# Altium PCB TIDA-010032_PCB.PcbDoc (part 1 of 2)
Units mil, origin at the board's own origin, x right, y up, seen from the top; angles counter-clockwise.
Board outline 5930.03 x 5930.03 mil, 2 copper layers (Top Layer, Bottom Layer), stack 62 mil thick; 61 components, 49 nets, 261 pads, 71 vias.
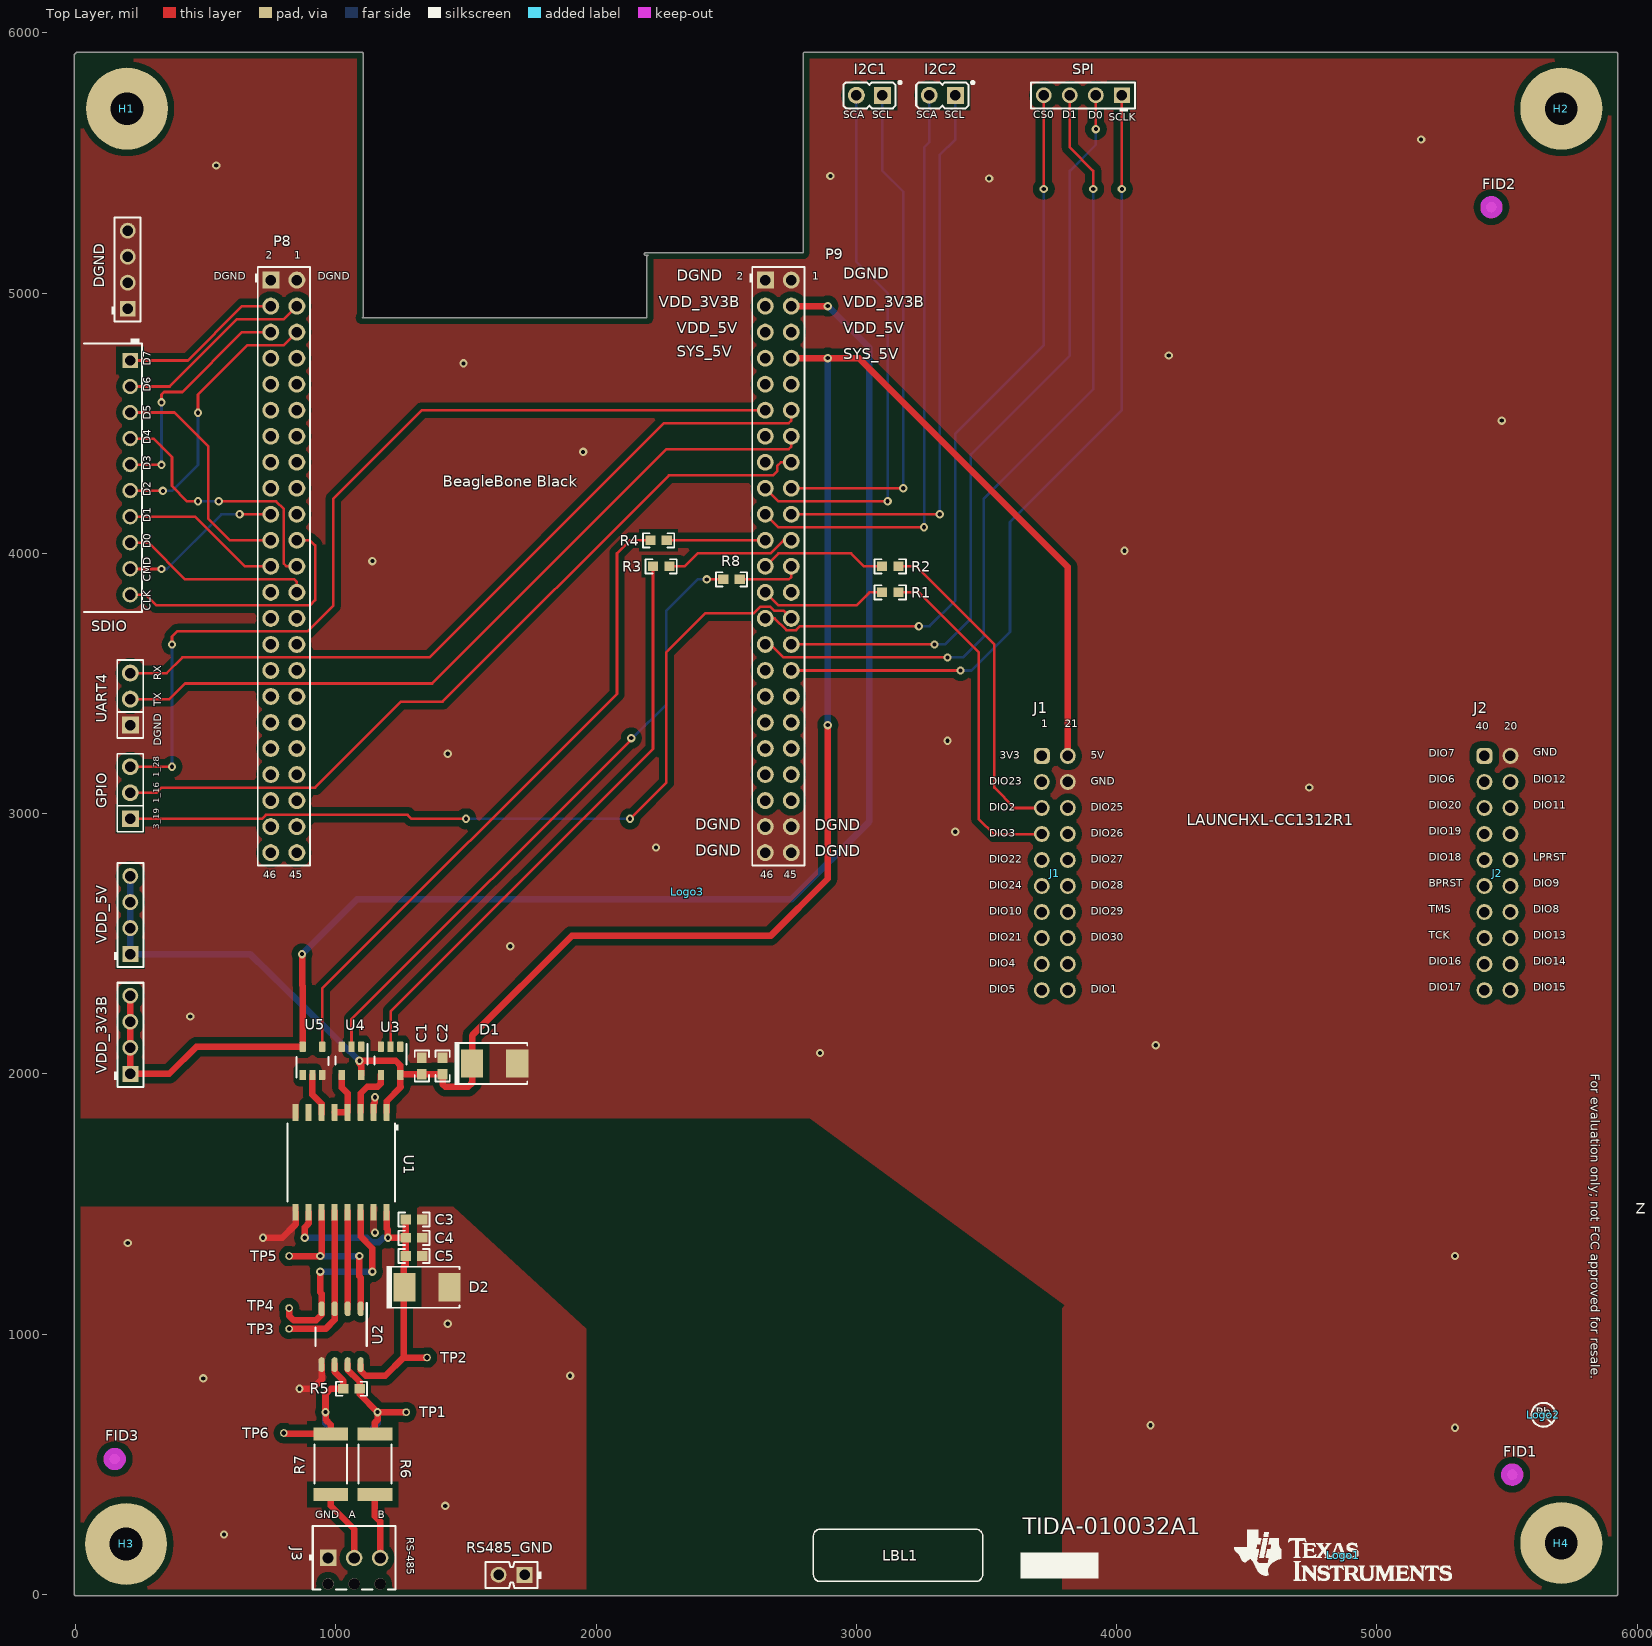
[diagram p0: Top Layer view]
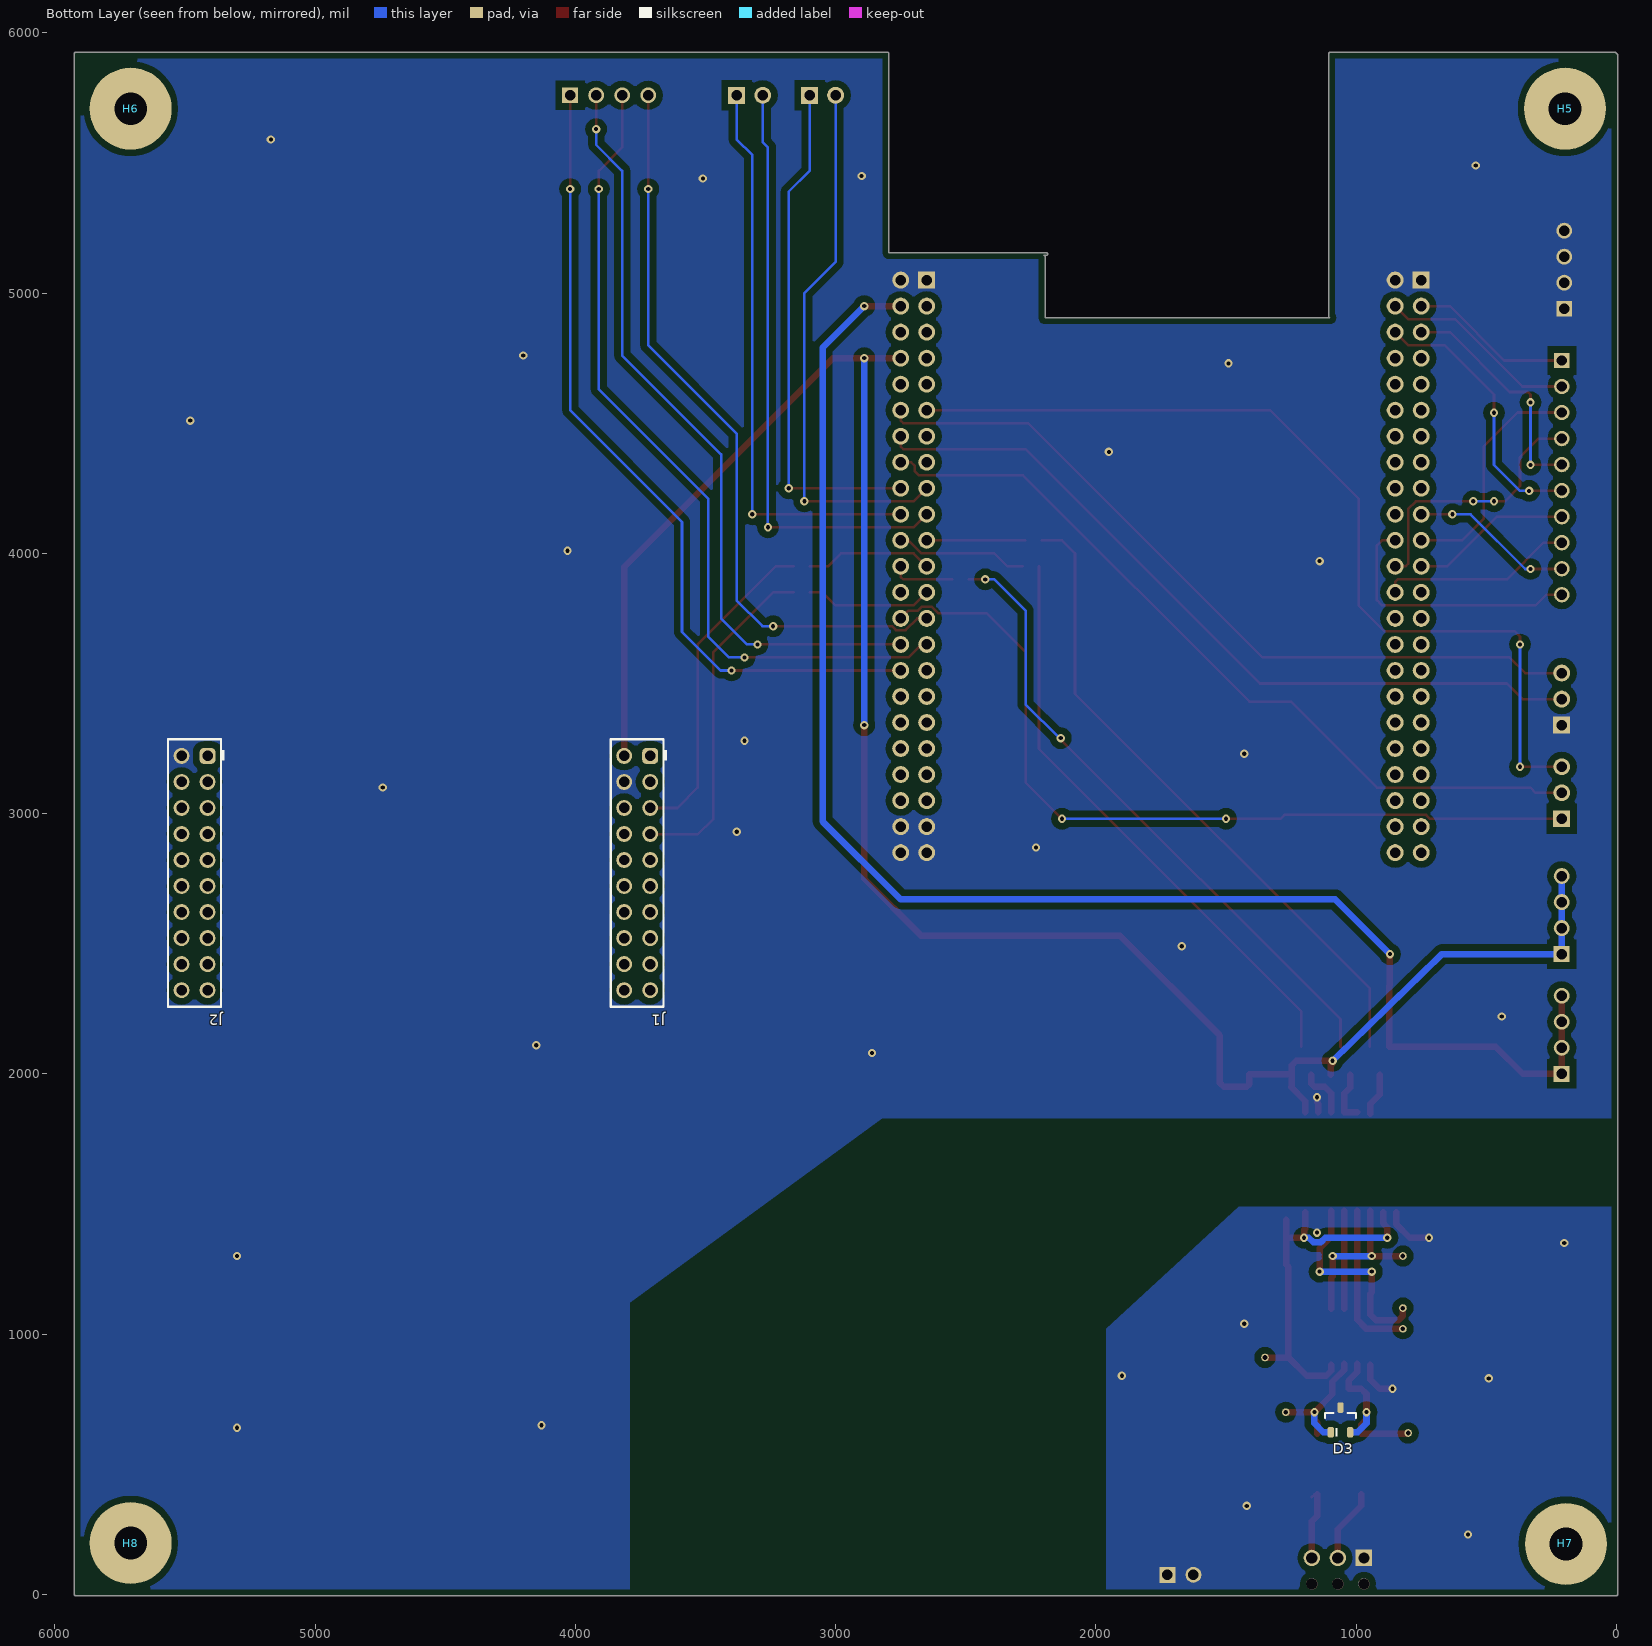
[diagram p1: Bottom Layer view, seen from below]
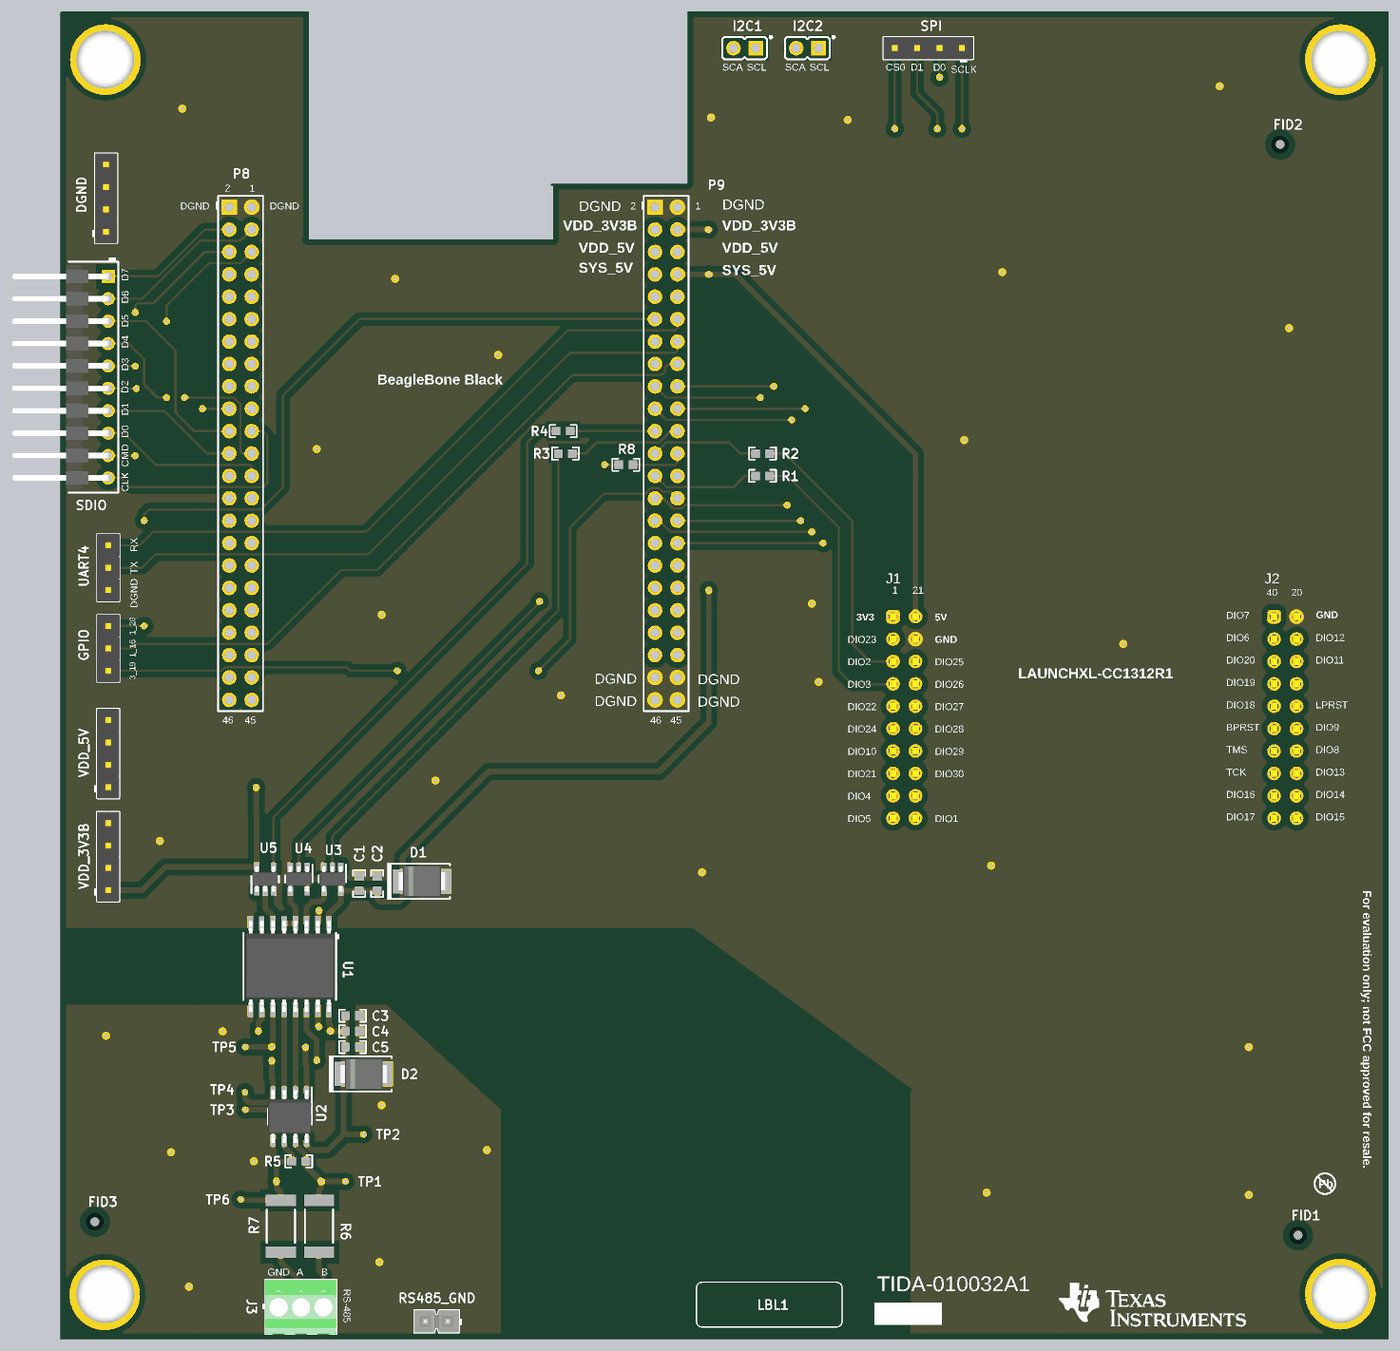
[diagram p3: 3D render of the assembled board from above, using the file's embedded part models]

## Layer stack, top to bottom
Top Solder: solder mask 0.4, Solder Resist, Dk 3.5
Top Layer: signal copper 1.4
Dielectric1: core 59.2, FR-4, Dk 4.8
Bottom Layer: signal copper 1.4
Bottom Solder: solder mask 0.4, Solder Resist, Dk 3.5

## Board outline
0,-5.02 cw(c0,0) -5.01,0 -5.01,5915.02 cw(c0,5915.02) -0.03,5920.03 cw(c4.99,5920) 4.99,5925.02 1100,5925.02 cw(c1100,5920) 1105.02,5920 1105.02,4910 cw(c1100,4910) 1100.55,4905.02 2194.99,4905.02 2194.99,5140 cw(c2200,5140) 2199.45,5144.98 2190,5144.98 cw(c2190,5150) 2190,5155.02 2794.99,5155.02 2794.99,5920 cw(c2800,5920) 2800,5925.02 5920,5925.02 cw(c5920,5920) 5925.02,5920 5925.02,0 cw(c5920,0) 5920,-5.02

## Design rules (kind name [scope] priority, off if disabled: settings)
AcuteAngle [All] p1: minimum=4.50000000000000E+0001 checktracksonly=FALSE
AssemblyTestPointUsage [All] p1: valid=2
BoardOutlineClearance BoardOutlineClearance_MountingHoles [OnCopper and InComponentClass('Mounting Holes')] p1: gap=40
BoardOutlineClearance BoardOutlineClearance_Poly [OnCopper and IsPoly] p2: gap=25
BoardOutlineClearance [OnCopper and Not InComponentClass('Logo') and not InComponentClass('FiducialMark') and not InRegion(1000,500,4000,800) and not InPoly] p3: gap=15
Clearance Clearance_Keepouts [((IsTrack Or IsArc) And Not InPoly) And IsFree and IsKeepOut vs ((IsTrack Or IsArc) And Not InPoly) And IsFree and IsKeepOut] p1: gap=0
Clearance Clearance_Poly [InPolygon] p2: gap=25
Clearance [All] p3: gap=7.87
ComponentClearance ComponentClearance_MountingHoles_FiducialMarks [InComponentClass('Mounting Holes') vs InComponentClass('FiducialMark')] p1: gap=50 collisioncheckmode=3 verticalgap=10 showdistances=FALSE
ComponentClearance ComponentClearance_Shunt [InComponentClass('Header') vs InComponentClass('Shunt')] p2: gap=0 collisioncheckmode=3 verticalgap=0 showdistances=FALSE
ComponentClearance ComponentClearance_Logo [InComponentClass('Logo')] p3: gap=50 collisioncheckmode=3 verticalgap=10 showdistances=FALSE
ComponentClearance ComponentClearance_ScrewToNut [(HasFootprint('NY PMS 440 0025 PH')) vs (HasFootprint('Keystone_1902C'))] p4: gap=5 collisioncheckmode=3 verticalgap=10 showdistances=FALSE
ComponentClearance ComponentClearance_MountingHoles [InComponentClass('Mounting Holes')] p5: gap=250 collisioncheckmode=3 verticalgap=100000 showdistances=FALSE
ComponentClearance ComponentClearance_SmallPassives [HasFootprint('0201*') or HasFootprint('0402*') or HasFootprint('0508') or HasFootprint('0603*') or HasFootprint('0612') or HasFootprint('0805*') or HasFootprint('0815*') or HasFootprint('0830*') or HasFootprint('1206*') or HasFootprint('1210*') or HasFootprint('1808*') or HasFootprint('1812*') or HasFootprint('1825*') or HasFootprint('2010*') or HasFootprint('2220*') or HasFootprint('2225*') or HasFootprint('2512*') or HasFootprint('2728*') or HasFootprint('3518*') vs HasFootprint('0201*') or HasFootprint('0402*') or HasFootprint('0508') or HasFootprint('0603*') or HasFootprint('0612') or HasFootprint('0805*') or HasFootprint('0815*') or HasFootprint('0830*') or HasFootprint('1206*') or HasFootprint('1210*') or HasFootprint('1808*') or HasFootprint('1812*') or HasFootprint('1825*') or HasFootprint('2010*') or HasFootprint('2220*') or HasFootprint('2225*') or HasFootprint('2512*') or HasFootprint('2728*') or HasFootprint('3518*')] p6: gap=14.96 collisioncheckmode=3 verticalgap=10 showdistances=FALSE
ComponentClearance ComponentClearance_THtoSMT [IsThruComponent vs IsSMTComponent] p7: gap=40 collisioncheckmode=3 verticalgap=30 showdistances=FALSE
ComponentClearance ComponentClearance_THtoTH [IsThruComponent vs IsThruComponent] p8: gap=30 collisioncheckmode=3 verticalgap=30 showdistances=FALSE
ComponentClearance [All] p9: gap=30 collisioncheckmode=3 verticalgap=10 showdistances=FALSE
DiffPairsRouting [All] p1: maxlimit=100 minlimit=10 mostfreqgap=10 toplayer_minwidth=15 toplayer_maxwidth=15 toplayer_prefwidth=15 bottomlayer_minwidth=15 bottomlayer_maxwidth=15 bottomlayer_prefwidth=15 maxuncoupledlength=1000
FabricationTestPointUsage TestPointUsage [All] p1: valid=2 allowmultiple=FALSE
FabricationTestpoint Testpoint [All] p1: side=3 testpointundercomponent=TRUE minsize=40 maxsize=100 preferedsize=60 minholesize=0 maxholesize=40 preferedholesize=32 testpointgrid=1 allowsidetop=TRUE allowsidebottom=TRUE usegrid=TRUE gridtolerance=0.01
FanoutControl Fanout_LCC [IsLCC] p1: bgadir=Out bgaviamode=Centered fanoutstyle=Auto fanoutdirection=Alternating viagrid=1 // Fanout_LCC (Default Rule)
FanoutControl Fanout_BGA [IsBGA] p2: bgadir=Out bgaviamode=Centered fanoutstyle=Auto fanoutdirection=Alternating viagrid=1 // Fanout_BGA (Default Rule)
FanoutControl Fanout_Default [All] p4: bgadir=Out bgaviamode=Centered fanoutstyle=Auto fanoutdirection=Alternating viagrid=1 // Fanout_Default (Default Rule)
FanoutControl Fanout_Small [(CompPinCount < 5)] p5: bgadir=Out bgaviamode=Centered fanoutstyle=Auto fanoutdirection=OutThenIn viagrid=1 // Fanout_Small (Default Rule)
HoleSize [All] p1: absolutevalues=TRUE maxlimit=251 minlimit=7.87 maxpercent=80.000 minpercent=20.000
MinimumAnnularRing MinimumAnnularRing_ThermalPadVias [IsVia and InAnyComponent] p1: minimumring=5.91
MinimumAnnularRing [All] p2: minimumring=2
MinimumSolderMaskSliver MinimumSolderMaskSliver_Logo [InComponentClass('Logo') vs InComponentClass('Logo')] p1: minsoldermaskwidth=0.7
MinimumSolderMaskSliver [All] p2: minsoldermaskwidth=3.94
PlaneConnect [All] p1: planeconnectstyle=Direct reliefexpansion=10 reliefentries=4 reliefconductorwidth=10 reliefairgap=10
PolygonConnect [All] p1: connectstyle=Direct reliefconductorwidth=10 reliefentries=4 polygonreliefangle="90 Angle" airgapwidth=10
RoutingVias ThermalPadVias [IsVia and InAnyComponent] p1: holewidth=7.87 width=19.68 viastyle="Through Hole" minholewidth=7.87 minwidth=19.68 maxholewidth=12.99 maxwidth=23.62
RoutingVias [All] p2: holewidth=16 width=34 viastyle="Through Hole" minholewidth=7.87 minwidth=26 maxholewidth=40 maxwidth=65
SilkToBoardRegionClearance [Not ((IsComment or IsDesignator) And (Hide <> 'False')) and not InRegion(1000,500,4000,800)] p1:
SilkToSilkClearance SilkToSilkClearance_Pb-FreeLogo [(HasFootprint('Pb-Free_Overlay_Medium') OR HasFootprint('Pb-Free_Overlay_Small')) vs (HasFootprint('Pb-Free_Overlay_Medium') OR HasFootprint('Pb-Free_Overlay_Small'))] p1: silktosilkclearance=0
SilkToSilkClearance [All] p2: silktosilkclearance=4
SilkToSolderMaskClearance SilkToComponentPadClearance [(IsPad or IsFill or IsRegion) and InAnycomponent] p1: minsilkscreentomaskgap=5 clearancetoexposedcopper=TRUE
SilkToSolderMaskClearance "Silk to Solder Mask Opening" [All] p2: minsilkscreentomaskgap=4 clearancetoexposedcopper=FALSE
SolderMaskExpansion [All] p1: expansion=1.97
Width [All] p1: maxlimit=100 minlimit=6 preferedwidth=10 checkconnectedcopper=TRUE
15 further rules are at their usual default settings.

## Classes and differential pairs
component class TIDA-010032_1: DGND GPIO I2C1 I2C2 J1 J2 P8 P9 R1 R2 R3 R4 R8 SDIO SPI UART4 VDD_3V3B VDD_5V
component class Label: LBL1
component class AssemblyNote: ZZ1 ZZ2 ZZ3 ZZ4
component class FiducialMark: FID1 FID2 FID3
component class TIDA-010032_EVM_Hardware: FID1 FID2 FID3 H1 H2 H3 H4 H5 H6 H7 H8 LBL1 Logo1 Logo2 Logo3 ZZ1 ZZ2 ZZ3 ZZ4
component class Logo: Logo1
component class "Mounting Holes": H1 H2 H3 H4
component class Header: DGND GPIO I2C1 I2C2 P8 P9 RS485_GND SDIO SPI UART4 VDD_3V3B VDD_5V
component class TIDA-010032_2: C1 C2 C3 C4 C5 D1 D2 D3 J3 R5 R6 R7 RS485_GND TP1 TP2 TP3 TP4 TP5 TP6 U1 U2 U3 U4 U5

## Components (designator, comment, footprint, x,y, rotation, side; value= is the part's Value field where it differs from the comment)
C1 "C0603C104J4RACTU" 0603 1330,2030 r90 top
C2 "C0603C106M9PACTU" 0603 1410,2030 r270 top
C3 "C0603C104J4RACTU" 0603 1300,1440 r0 top
C4 "C0603C106M9PACTU" 0603 1300,1370 r180 top
C5 "C0603C104J4RACTU" 0603 1300,1300 r0 top
D1 "1SMB5919BT3G" SMB 1610,2040 r0 top
D2 "1SMB5919BT3G" SMB 1350,1180 r0 top
D3 "CDSOT23-SM712" SOT-23 1060,670 r90 bottom
DGND "PBC04SAAN" Sullins_xxC04SAAN 200,5090 r90 top
FID1 "Fiducial" Fiducial10-20 5520,460 r0 top
FID2 "Fiducial" Fiducial10-20 5440,5330 r0 top
FID3 "Fiducial" Fiducial10-20 150,520 r0 top
GPIO "PBC03SAAN" PBC03SAAN 210,3080 r90 top
H1 "NY PMS 440 0025 PH" "NY PMS 440 0025 PH"#1 196.85,5708.66 r0 top locked
H2 "NY PMS 440 0025 PH" "NY PMS 440 0025 PH"#1 5708.66,5708.66 r0 top locked
H3 "NY PMS 440 0025 PH" "NY PMS 440 0025 PH"#2 196.85,196.85 r0 top locked
H4 "NY PMS 440 0025 PH" "NY PMS 440 0025 PH"#1 5708.66,196.85 r0 top locked
H5 "1902C" Keystone_1902C 196.85,5708.66 r180 bottom locked
H6 "1902C" Keystone_1902C 5708.66,5708.66 r180 bottom locked
H7 "1902C" Keystone_1902C 196.85,196.85 r180 bottom locked
H8 "1902C" Keystone_1902C 5708.66,196.85 r180 bottom locked
I2C1 "PBC02SAAN" Sullins_PBC02SAAN 3050,5760 r270 top
I2C2 "PBC02SAAN" Sullins_PBC02SAAN 3330,5760 r270 top
J1 "SSQ-110-23-L-D" Samtec_SSQ-110-23-x-D 3762.5,2771.65 r270 top locked
J2 "SSQ-110-23-L-D" Samtec_SSQ-110-23-x-D 5463.15,2771.65 r270 top locked
J3 "1725669" Phoenix_1725669 1070,140 r0 top
LBL1 "Size: 0.65\" x 0.20 \"" Label_650x200 3160,150 r0 top
Logo1 "Texas Instruments" TI_Stacked_Overlay_Small 4870,150 r0 top
Logo2 "Pb-Free Symbol" Pb-Free_Overlay_Small 5640,690 r0 top
Logo3 "FCC disclaimer" FCC_disclaimer 2350,2700 r0 top
P8 "PBC23DFAN" Sullins_PBC23DFAN 800,3950 r0 top locked
P9 "PBC23DFAN" Sullins_PBC23DFAN 2700,3950 r0 top locked
R1 "ERJ-3GEY0R00V" 0603 3130,3850 r180 top
R2 "ERJ-3GEY0R00V" 0603 3130,3950 r180 top
R3 "ERJ-3GEY0R00V" 0603 2250,3950 r180 top
R4 "ERJ-3GEY0R00V" 0603 2240,4050 r0 top
R5 "CRCW0603120RJNEA" 0603 1060,790 r180 top
R6 "CRCW251210R0FKEG" 2512 1150,500 r270 top
R7 "CRCW251210R0FKEG" 2512 980,500 r270 top
R8 "ERJ-3GEY0R00V" 0603 2520,3900 r180 top
RS485_GND "TSW-102-07-T-S" Samtec_TSW-102-07-T-S 1675,75 r180 top
SDIO "M20-9961045" Harwin_M20-9961045 20.47,4291 r0 top
SPI "PBC04SAAN" Sullins_xxC04SAAN 3870,5760 r180 top
TP1 "TP_H0.45P0.75" TP_H045P075 1270,700 r0 top
TP2 "TP_H0.45P0.75" TP_H045P075 1350,910 r0 top
TP3 "TP_H0.45P0.75" TP_H045P075 820,1020 r0 top
TP4 "TP_H0.45P0.75" TP_H045P075 820,1100 r0 top
TP5 "TP_H0.45P0.75" TP_H045P075 820,1300 r0 top
TP6 "TP_H0.45P0.75" TP_H045P075 799.89,620 r0 top
U1 "ISOW7841FDWER" DWE0016A 1020,1660 r270 top
U2 "THVD1500DR" D0008A_N 1020,990 r270 top
U3 "SN74LV1T34DBVR" DBV0005A_N 1210,2050 r270 top
U4 "SN74LV1T34DBVR" DBV0005A_N 1060,2050 r270 top
U5 "SN74LV1T34DBVR" DBV0005A_N 910,2050 r90 top
UART4 "PBC03SAAN" PBC03SAAN 210,3440 r90 top
VDD_3V3B "PBC04SAAN" Sullins_xxC04SAAN 210,2150 r90 top
VDD_5V "PBC04SAAN" Sullins_xxC04SAAN 210,2610 r90 top
ZZ1 "This Assembly Note is for PCB labels only" AssemblyNoteLabel 6538,166 r90 top
ZZ2 "These assemblies are ESD sensitive, ESD precautions shall be observed." AssemblyNote 6358,2646 r90 top
ZZ3 "These assemblies must be clean and free from flux and all contaminants. Use of no clean flux is not acceptable." AssemblyNote 6188,1086 r90 top
ZZ4 "These assemblies must comply with workmanship standards IPC-A-610 Class 2, unless otherwise specified." AssemblyNote 6008,1416 r90 top

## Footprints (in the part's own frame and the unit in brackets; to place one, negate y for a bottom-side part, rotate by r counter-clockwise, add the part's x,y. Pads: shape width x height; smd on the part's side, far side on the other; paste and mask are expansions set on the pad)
0603 [mm] "0603 from SM-752 data"
  rect 1x0.95 smd: 1(-0.8,0) 2(0.8,0)
  silkscreen extent -1.52,-0.69 1.52,0.69, body extent -0.87,-0.47 0.87,0.47, height 1
2512 [mm] "Chip Resistor, Body 6.3x3.2mm, IPC Medium Density"
  rect 1.3x3.4 smd: 1(-2.95,0) 2(2.95,0)
  silkscreen extent -1.9,-1.6 1.9,1.6, body extent -3.22,-1.67 3.22,1.67, height 0.71
AssemblyNote [mil] "Assembly Note"
AssemblyNoteLabel [mil] "Assembly Note for PCB Labels"
D0008A_N [mm] "SOIC, 8-Leads, Body 4.9x3.9mm, Pitch 1.27mm, IPC Medium Density"
  oval 1.45x0.6 smd: 1(-2.725,1.905) 2(-2.725,0.635) 3(-2.725,-0.635) 4(-2.725,-1.905) 5(2.725,-1.905) 6(2.725,-0.635) 7(2.725,0.635) 8(2.725,1.905)
  silkscreen extent -3.3,-2.5 0.9,2.5, body extent -3,-2.45 3,2.45, height 1.63
DBV0005A_N [mm] "SOT23, 5-Leads, Body 2.9x1.6mm, Pitch 0.95mm, Lead Span 2.8mm, IPC Medium Density"
  rrect17% 1x0.6 smd: 1(-1.375,0.95) 2(-1.375,0) 3(-1.375,-0.95) 4(1.375,-0.95) 5(1.375,0.95)
  silkscreen extent -1.63,-1.55 0.38,1.55, body extent -1.42,-1.46 1.42,1.46, height 1.09
DWE0016A [mm] "SOIC, 16-Leads, Body 10.5x7.6mm, Pitch 1.27mm"
  rrect17% 1.65x0.6 smd: 1(-4.875,4.445) 2(-4.875,3.175) 3(-4.875,1.905) 4(-4.875,0.635) 5(-4.875,-0.635) 6(-4.875,-1.905) 7(-4.875,-3.175) 8(-4.875,-4.445) 9(4.875,-4.445) 10(4.875,-3.175) 11(4.875,-1.905) 12(4.875,-0.635) 13(4.875,0.635) 14(4.875,1.905) 15(4.875,3.175) 16(4.875,4.445)
  silkscreen extent -3.8,-5.25 3.8,5.6, body extent -5.17,-5.15 5.17,5.15, height 2.59
FCC_disclaimer [mil]
Fiducial10-20 [mm]
  round 1 smd mask+0.5: 1(0,0)
  Top Layer keep-out circle w1.178: c0,0 r0.5
Harwin_M20-9961045 [mm] "Header, 2.54 mm, 10x1, TH"
  rect 1.5x1.5 hole 1: 1(4.8,11.43)
  round 1.5 hole 1: 2(4.8,8.89) 3(4.8,6.35) 4(4.8,3.81) 5(4.8,1.27) 6(4.8,-1.27) 7(4.8,-3.81) 8(4.8,-6.35) 9(4.8,-8.89) 10(4.8,-11.43)
  silkscreen extent 0.31,-13.1 5.95,13.6, body extent -6.1,-12.7 5.12,12.7, height 2.54
Keystone_1902C [mil] "Hex Standoff, 4-40 threaded, nylon"
  body extent -145,-126 146,126, height 501
Label_650x200 [mil] "Thermal Transfer Label"
  silkscreen extent -325,-100 325,100, body extent -325,-100 325,100, height 1
"NY PMS 440 0025 PH"#1 [mm] "4-40 nylon screw and mounting hole"
  round 8 hole 3.2: 1(0,0)
  body extent -3.3,-3.3 3.3,3.3, height 2.69
"NY PMS 440 0025 PH"#2 [mm] "4-40 nylon screw and mounting hole"
  round 8 hole 3.2: 1(-0.08,-0.08)
  body extent -3.3,-3.3 3.3,3.3, height 2.69
Pb-Free_Overlay_Small [mil]
  silkscreen extent -46,-46 46,46
PBC03SAAN [mm] "Sullins 100mil, 1x3, 230 mil above insulator"
  rect 1.65x1.65 hole 1.016: 1(-2.54,0)
  round 1.65 hole 1.016: 2(0,0) 3(2.54,0)
  silkscreen extent -3.81,-1.27 3.81,1.27, body extent -3.81,-1.27 3.81,1.27, height 8.38
Phoenix_1725669 [mm] "Terminal Block, 3x1, 2.54 mm, TH"
  rect 1.6x1.6 hole 1.1: 1(-2.54,0)
  round 1.6 hole 1.1: 2(0,0) 3(2.54,0)
  round 1.1 hole 1.1 unplated mask+0: 4(-2.54,-2.54) 5(0,-2.54) 6(2.54,-2.54)
  silkscreen extent -4.4,-3.1 4.04,3.1, body extent -4.04,-3.1 4.04,3.1, height 8.5
Samtec_SSQ-110-23-x-D [mm] "Receptacle, 2.54mm, 10x2, TH"
  rrect50% 1.55x1.55 hole 1.02: 1(-11.43,-1.27)
  round 1.55 hole 1.02: 2(-11.43,1.27) 3(-8.89,-1.27) 4(-8.89,1.27) 5(-6.35,-1.27) 6(-6.35,1.27) 7(-3.81,-1.27) 8(-3.81,1.27) 9(-1.27,-1.27) 10(-1.27,1.27) 11(1.27,-1.27) 12(1.27,1.27) 13(3.81,-1.27) 14(3.81,1.27) 15(6.35,-1.27) 16(6.35,1.27) 17(8.89,-1.27) 18(8.89,1.27) 19(11.43,-1.27) 20(11.43,1.27)
  body extent -12.95,-2.48 12.95,2.48, height 8.51
Samtec_TSW-102-07-T-S [mm] "Header, 2.54 mm, 2x1, Tin, TH"
  rect 1.55x1.55 hole 1.02: 1(-1.27,0)
  round 1.55 hole 1.02: 2(1.27,0)
  silkscreen extent -2.9,-1.27 2.54,1.27, body extent -2.54,-1.27 2.54,1.27, height 8.38
SMB [mil] "Molded Diode, 2-Leads, Body 5.4x3.6mm, IPC Medium Density, based on OnSemi component dimensions"
  rect 85x107.99 smd: 1(-87.01,0) 2(87.01,0)
  silkscreen extent -155,-82 125,82, body extent -106,-71 106,71, height 91
SOT-23 [mm] "SOT23, 3-Leads, Body 2.9x1.3mm, Pitch 0.95mm, Lead Span 2.5mm, IPC Medium Density"
  rrect50% 1x0.6 smd: 1(-1.2,0.95) 2(-1.2,-0.95) 3(1.2,0)
  silkscreen extent -1.62,-1.5 0.7,1.5, body extent -1.16,-1.45 1.21,1.45, height 1
Sullins_PBC02SAAN [mm] "Sullins 100mil, 1x2, 230 mil above insulator"
  rect 1.65x1.65 hole 1.016: 1(0,1.27)
  round 1.65 hole 1.016: 2(0,-1.27)
  silkscreen extent -1.37,-2.54 1.27,3.1, body extent -1.27,-2.54 1.27,2.54, height 8.38
Sullins_PBC23DFAN [mm] "Header, 100mil, 23x2, TH"
  rect 1.65x1.65 hole 1.016: 1(-1.27,27.94)
  round 1.65 hole 1.016: 2(1.27,27.94) 3(-1.27,25.4) 4(1.27,25.4) 5(-1.27,22.86) 6(1.27,22.86) 7(-1.27,20.32) 8(1.27,20.32) 9(-1.27,17.78) 10(1.27,17.78) 11(-1.27,15.24) 12(1.27,15.24) 13(-1.27,12.7) 14(1.27,12.7) 15(-1.27,10.16) 16(1.27,10.16) 17(-1.27,7.62) 18(1.27,7.62) 19(-1.27,5.08) 20(1.27,5.08) 21(-1.27,2.54) 22(1.27,2.54) 23(-1.27,0) 24(1.27,0) 25(-1.27,-2.54) 26(1.27,-2.54) 27(-1.27,-5.08) 28(1.27,-5.08) 29(-1.27,-7.62) 30(1.27,-7.62) 31(-1.27,-10.16) 32(1.27,-10.16) 33(-1.27,-12.7) 34(1.27,-12.7) 35(-1.27,-15.24) 36(1.27,-15.24) 37(-1.27,-17.78) 38(1.27,-17.78) 39(-1.27,-20.32) 40(1.27,-20.32) 41(-1.27,-22.86) 42(1.27,-22.86) 43(-1.27,-25.4) 44(1.27,-25.4) 45(-1.27,-27.94) 46(1.27,-27.94)
  silkscreen extent -2.79,-29.21 2.54,29.21, body extent -2.54,-29.21 2.54,29.21, height 10.62
Sullins_xxC04SAAN [mm] "Header, 2.54 mm, 4x1, TH"
  rect 1.55x1.55 hole 1.016: 1(-3.81,0)
  round 1.55 hole 1.016: 2(-1.27,0) 3(1.27,0) 4(3.81,0)
  silkscreen extent -5.08,-1.27 5.08,1.6, body extent -5.08,-1.27 5.08,1.27, height 8.38
TI_Stacked_Overlay_Small [mil]
  silkscreen extent -418,-98 418,98
TP_H045P075 [mm] "TP_H0.45P0.75"
  round 0.75 hole 0.45: 1(0,0)

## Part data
C1 C3 C5: "CAP, CERM, 0.1uF, 16V, +/-5%, X7R, 0603"
C2 C4: "CAP, CERM, 10 µF, 6.3 V, +/- 20%, X5R, 0603"
D1 D2: "Diode, Zener, 5.6 V, 550 mW, SMB"
D3: library part CMP-0005928-2, "Diode, TVS, Bi, 7 V, SOT-23"
DGND SPI VDD_3V3B VDD_5V: library part CMP-0054583-1, "Header, 2.54 mm, 4x1, Gold, TH"
FID1 FID2 FID3: "Fiducial mark.  There is nothing to buy or mount."
GPIO UART4: library part CMP-0002334-1, "Header, 100mil, 3x1, Gold, TH"
H1 H2 H3 H4: "Machine Screw, Round, #4-40 x 1/4, Nylon, Philips panhead"
H5 H6 H7 H8: "Standoff, Hex, 0.5\"L #4-40 Nylon"
I2C1 I2C2: library part CMP-0054566-1, "Header, 100mil, 2x1, Gold, TH"
J1 J2: library part CMP-0055702-1, "Receptacle, 2.54mm, 10x2, Gold, TH"
J3: "Terminal Block, 3x1, 2.54 mm, TH"
LBL1: library part THT-14-423-10, "Thermal Transfer Printable Labels, 0.650\" W x 0.200\" H - 10,000 per roll"
Logo1: library part TI_Logo, "Texas Instrument Corporate Signature"
Logo2: library part Pb-Free
Logo3: library part FCC_disclaimer, "FCC_disclaimer"
P8 P9: library part CMP-0054573-1, "Header, 100 mil, 23x2, Gold, TH"
R1 R2 R3 R4 R8: library part CMP-0025874-4, "RES, 0, 5%, 0.1 W, AEC-Q200 Grade 0, 0603"
R5: "RES, 120 ohm, 5%, 0.1W, 0603"
R6 R7: "RES, 10.0, 1%, 1 W, AEC-Q200 Grade 0, 2512"
RS485_GND: "Header, 2.54 mm, 2x1, Tin, TH"
SDIO: library part CMP-0075170-1, "Header, 2.54 mm, 10x1, TH"
TP1 TP2 TP3 TP4 TP5 TP6: library part CMP-0003719-1, "Testpoint"
U1: library part CMP-0082564-1, "High-Efficiency, Low-Emissions, Reinforced Digital Isolator With Integrated Power, DWE0016A (SO-MOD-16)"
U2: library part CMP-0013008-2, "250 kbps RS-485 Transceivers With +/-12-kV IEC ESD Protection, D0008A (SOIC-8)"
U3 U4 U5: "Single Power Supply BUFFER Logic Level Shifter (no enable), DBV0005A (SOT-5)"
ZZ1: library part AssemblyNoteLabel
ZZ2 ZZ3 ZZ4: library part AssemblyNote

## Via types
v1: diameter 32, hole 16, Top Layer to Bottom Layer, 71 vias

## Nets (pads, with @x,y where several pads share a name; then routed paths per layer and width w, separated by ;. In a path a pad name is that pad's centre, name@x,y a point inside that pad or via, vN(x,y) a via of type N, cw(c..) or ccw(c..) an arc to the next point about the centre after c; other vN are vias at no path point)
DGND: C1.2 C2.1 D1.2 DGND.1 DGND.2 DGND.3 DGND.4 J1.4 J2.2 P8.1 P8.2 P9.1 P9.2 P9.43 P9.44 P9.45 P9.46 U1.2 U1.8 U3.3 U4.3 U5.3 UART4.1 | length 60.1
  Top Layer w25: U1.2@1145,1851.93 1145,1885 1150,1890 v1(1150,1910)
  other v1: 5300,640 4130,650 5300,1300 2860,2080 4150,2110 440,2220 1670,2490 2230,2870 3380,2930 4740,3100 1430,3230 3350,3280 1140,3970 4030,4010 1950,4390 5480,4510 1490,4730 4200,4760 3510,5440 2900,5450 540,5490 5170,5590
GPIO1_16: GPIO.2 P9.16 | length 3077.8
  Top Layer w10: GPIO.2@210,3080 310,3080 330,3100 920,3100 1250,3430 1410,3430 2280,4300 2680,4300 2695.35,4315.35 2695.35,4335.35 2710,4350 P9.16@2750,4350
GPIO1_17: R8.2 U4.2 | length 2448.2
  Top Layer w10: U4.2@1060,2104.13 1060,2210 2135,3285 v1(2135,3290) ; v1(2425,3900) R8.2@2488.5,3900
  Bottom Layer w10: v1(2135,3290) 2140,3290 2270,3420 2270,3780 2390,3900 v1(2425,3900)
GPIO1_28: GPIO.3 P9.11 | length 3541
  Top Layer w10: GPIO.3@210,3180 v1(370,3180) ; v1(370,3650) 370,3680 390,3700 890.78,3700 990,3799.22 990,4210 1330,4550 P9.11@2650,4550
  Bottom Layer w10: v1(370,3180) v1(370,3650)
GPIO3_19: GPIO.1 P9.28 | length 3202.1
  Top Layer w10: GPIO.1@210,2980 715.86,2980 731.21,2995.35 1275.35,2995.35 1290.71,2980 v1(1500,2980) ; v1(2130,2980) 2270,3120 2270,3620 2420,3770 2605.86,3770 2631.21,3795.35 2668.79,3795.35 2684.14,3780 2720,3780 P9.28@2750,3750
  Bottom Layer w10: v1(1500,2980) v1(2130,2980)
I2C1_SCA: I2C1.2 P9.17 | length 2100.4
  Top Layer w10: P9.17@2650,4250 2700,4200 v1(3120,4200)
  Bottom Layer w10: I2C1.2@3000,5760 3000,5120 3120,5000 v1(3120,4200)
I2C1_SCL: I2C1.1 P9.18 | length 1973.1
  Top Layer w10: P9.18@2750,4250 v1(3180,4250)
  Bottom Layer w10: I2C1.1@3100,5760 3100,5470 3180,5390 v1(3180,4250)
I2C2_SCA: I2C2.2 P9.19 | length 2299
  Top Layer w10: P9.19@2650,4150 2700,4100 v1(3260,4100)
  Bottom Layer w10: v1(3260,4100) 3260,5560 3280,5580 I2C2.2@3280,5760
I2C2_SCL: I2C2.1 P9.20 | length 2204.9
  Top Layer w10: P9.20@2750,4150 v1(3320,4150)
  Bottom Layer w10: v1(3320,4150) 3320,5530 3380,5590 I2C2.1@3380,5760
MMC1_CLK: P8.22 SDIO.10 | length 1024.1
  Top Layer w10: SDIO.10@209.45,3841 269,3841 310,3800 900,3800 920,3820 920,4030 900,4050 P8.22@850,4050
MMC1_CMD: P8.19 SDIO.9 | length 626.5
  Top Layer w10: SDIO.9@210.45,3940 v1(330,3940) ; v1(630,4150) P8.19@750,4150
  Bottom Layer w10: v1(330,3940) 350,3940 560,4150 v1(630,4150)
MMC1_DAT0: P8.26 SDIO.8 | length 743.1
  Top Layer w10: SDIO.8@209.45,4041 279,4041 420,3900 840,3900 850,3890 P8.26@850,3850
MMC1_DAT1: P8.23 SDIO.7 | length 619.7
  Top Layer w10: SDIO.7@209.45,4141 210.45,4140 460,4140 650,3950 P8.23@750,3950
MMC1_DAT2: P8.6 SDIO.6 | length 1051.4
  Top Layer w10: SDIO.6@209.45,4241 v1(335,4240) ; v1(470,4540) 470,4610 660,4800 800,4800 P8.6@850,4850
  Bottom Layer w10: v1(335,4240) 370,4240 470,4340 v1(470,4540)
MMC1_DAT3: P8.5 SDIO.5 | length 910
  Top Layer w10: SDIO.5@209.45,4341 v1(330,4340) ; v1(330,4580) 330,4610 340,4620 410,4620 640,4850 P8.5@750,4850
  Bottom Layer w10: v1(330,4340) v1(330,4580)
MMC1_DAT4: P8.24 SDIO.4 | length 1032.2
  Top Layer w10: SDIO.4@209.45,4441 299,4441 370,4370 370,4258.65 428.65,4200 v1(470,4200) ; v1(550,4200) 770,4200 800,4170 800,3960 810,3950 P8.24@850,3950
  Bottom Layer w10: v1(470,4200) v1(550,4200)
MMC1_DAT5: P8.21 SDIO.3 | length 906.3
  Top Layer w10: SDIO.3@209.45,4541 379,4541 510,4410 510,4132.79 592.79,4050 P8.21@750,4050
MMC1_DAT6: P8.4 SDIO.2 | length 768.5
  Top Layer w10: SDIO.2@209.45,4641 361,4641 620,4900 800,4900 P8.4@850,4950
MMC1_DAT7: P8.3 SDIO.1 | length 627.1
  Top Layer w10: SDIO.1@209.45,4741 431,4741 640,4950 P8.3@750,4950
NetC3_1: C3.1 C4.2 C5.1 D2.1 TP2.1 U1.10 U1.16 U2.8 | length 1455.2
  Top Layer w25: v1(880,1370) 880,1410 895,1425 U1.10@895,1468.07 ; U2.8@1095,882.72 1095,859.6 1114.6,840 1190,840 1260,910 ; U1.16@1195,1468.07 1195,1405 1200,1400 v1(1200,1370) C4.2@1268.5,1370 ; C3.1@1268.5,1440 C4.2@1268.5,1370 ; TP2.1@1350,910 1260,910 ; 1260,910 1260,1258.5 1268.5,1267 C5.1@1268.5,1300 C4.2@1268.5,1370
  Bottom Layer w25: v1(880,1370) 1118.56,1370 1134.93,1353.63 1165.07,1353.63 1181.44,1370 v1(1200,1370)
NetD3_1: D3.1 R5.1 R6.1 TP1.1 U2.7 | length 552.1
  Top Layer w25: U2.7@1045,886.65 1045,863.11 1091.5,816.61 R5.1@1091.5,790 1091.5,768.5 v1(1160,700) ; R6.1@1150,616.14 1150,660 1160,670 v1(1160,700) ; TP1.1@1270,700 v1(1160,700)
  Bottom Layer w25: D3.1@1097.4,622.76 1125.79,622.76 1160,656.97 v1(1160,700)
NetD3_2: D3.2 R5.2 R7.1 TP6.1 U2.6 | length 645.5
  Top Layer w25: TP6.1@803.75,616.14 R7.1@980,616.14 980,651.57 961.57,670 961.57,698.43 v1(960,700) 960,770 980,790 R5.2@1028.5,790 1028.5,821.5 995,855 U2.6@995,886.65
  Bottom Layer w25: v1(960,700) 960,656.97 994.21,622.76 D3.2@1022.6,622.76
NetJ3_2: J3.2 R7.2 | length 281.1
  Top Layer w25: R7.2@980,383.86 980,340 1070,250 J3.2@1070,140
NetJ3_3: J3.3 R6.2 | length 266.3
  Top Layer w10: R6.2@1160,383.86 R6.2@1170,373.86
  Top Layer w25: R6.2@1150,383.86 1150,300 1170,280 J3.3@1170,140
NetP9_21: P9.21 R4.2 | length 378.5
  Top Layer w10: R4.2@2271.5,4050 P9.21@2650,4050
NetP9_22: P9.22 R3.1 | length 509.9
  Top Layer w10: R3.1@2281.5,3950 2340,3950 2390,4000 2420,4000 2670,4000 2720,4050 P9.22@2750,4050
NetP9_23: P9.23 R2.2 | length 489.9
  Top Layer w10: P9.23@2650,3950 2700,4000 2950,4000 2980,4000 3030,3950 R2.2@3098.5,3950
NetP9_24: P9.24 R8.1 | length 242.6
  Top Layer w10: R8.1@2551.5,3900 2740,3900 2750,3910 P9.24@2750,3950
NetP9_25: P9.25 R1.2 | length 489.9
  Top Layer w10: P9.25@2650,3850 2700,3800 2950,3800 3000,3800 3050,3850 R1.2@3098.5,3850
NetTP3_1: TP3.1 U1.12 U2.3 | length 607.5
  Top Layer w25: TP3.1@820,1020 960,1020 995,1055 U2.3@995,1097.28 U1.12@995,1468.07 U1.12@995,1472.99
NetTP4_1: TP4.1 U1.14 U2.4 | length 790.4
  Top Layer w25: TP4.1@820,1100 820,1070 837.13,1052.87 923.54,1052.87 945,1074.33 U2.4@945,1097.28 945,1155 940,1160 v1(940,1240) ; U1.14@1095,1472.99 1095,1375 1140,1330 v1(1140,1240)
  Bottom Layer w25: v1(940,1240) v1(1140,1240)
NetTP5_1: TP5.1 U1.11 U2.1 | length 649.9
  Top Layer w25: TP5.1@820,1300 v1(940,1300) 945,1305 U1.11@945,1468.07 U1.11@945,1472.99 ; v1(1090,1300) 1090,1222.12 1095,1217.12 U2.1@1095,1097.28
  Bottom Layer w25: v1(940,1300) v1(1090,1300)
NetU1_3: U1.3 U3.4 | length 199.5
  Top Layer w25: U1.3@1095,1851.93 1095,1925 1120,1950 1140,1950 1140.95,1950.95 1160.95,1950.95 1172.6,1962.6 U3.4@1172.6,1995.87
NetU1_4: U1.4 U1.5 U4.4 | length 203.2
  Top Layer w25: U1.5@995,1851.93 U1.4@1045,1851.93 1045,1925 1022.6,1947.4 U4.4@1022.6,1995.87
NetU1_6: U1.6 U5.2 | length 163.4
  Top Layer w25: U5.2@910,1995.87 910,1920 945,1885 U1.6@945,1847.01
NetU1_13: U1.13 U2.2 | length 375.7
  Top Layer w25: U2.2@1045,1097.28 U1.13@1045,1472.99
RS485_GND: C3.2 C4.1 C5.2 D2.2 D3.3 J3.1 RS485_GND.1 RS485_GND.2 U1.9 U1.15 U2.5 | length 354.2
  Top Layer w10: U2.5@945,882.72 U2.5@945,886.65
  Top Layer w25: v1(720,1370) 793.68,1370 845,1421.32 U1.9@845,1468.07 ; v1(860,790) 910,790 945,825 U2.5@945,882.72
  other v1: 570,230 1420,340 490,830 1900,840 1430,1040 200,1350 1150,1390
SPI1_CS0: P9.27 SPI.4 | length 2883.5
  Top Layer w10: P9.27@2650,3744.65 P9.27@2650,3750 2685.86,3750 2731.21,3704.65 2768.79,3704.65 2784.14,3720 v1(3240,3720) ; v1(3720,5400) SPI.4@3720,5760
  Bottom Layer w10: v1(3240,3720) 3281.35,3720 3380,3818.65 3380,4460 3720,4800 v1(3720,5400)
SPI1_D0: P9.30 SPI.2 | length 2940.2
  Top Layer w10: P9.30@2750,3650 v1(3300,3650) ; v1(3920,5630) SPI.2@3920,5760
  Bottom Layer w10: v1(3300,3650) 3340,3650 3440,3750 3440,4380 3820,4760 3820,5470 3920,5570 v1(3920,5630)
SPI1_D1: P9.29 SPI.3 | length 3185.1
  Top Layer w10: P9.29@2650,3650 2670,3650 2720,3600 v1(3350,3600) ; SPI.3@3820,5760 3820,5560 3910,5470 v1(3910,5400)
  Bottom Layer w10: v1(3350,3600) 3410,3600 3490,3680 3490,4210 3910,4630 v1(3910,5400)
SPI1_SCLK: P9.32 SPI.1 | length 3141
  Top Layer w10: P9.32@2750,3550 v1(3400,3550) ; v1(4020,5400) SPI.1@4020,5760
  Bottom Layer w10: v1(3400,3550) 3441.35,3550 3590,3698.65 3590,4120 4020,4550 v1(4020,5400)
